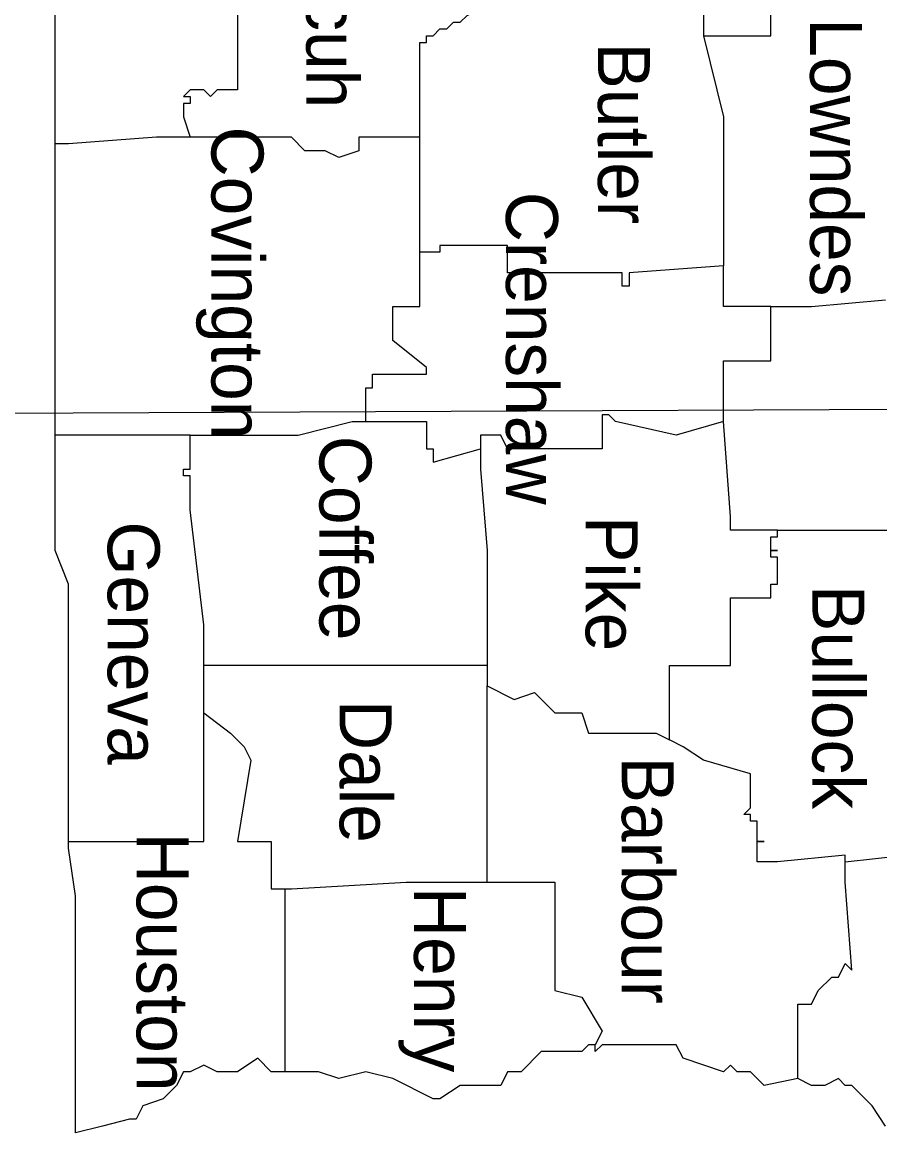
# Model space of a CAD drawing. Extents: x 0 to 0.917, y 0 to 0.708.
# Drawn here: x 0.3538 to 0.4398, y 0.4308 to 0.5421 of the extents above; entities that cross this region are included whole.
import ezdxf

# ---------------------------------------------------------------- set-up
doc = ezdxf.new("R2010")
doc.units = 0
doc.layers.add('ANNO-SHT', color=7, linetype='Continuous')
doc.layers.add('ANNO-TXT', color=7, linetype='Continuous')

msp = doc.modelspace()

# ---------------------------------------------------------------- linework, layer by layer
at = {"layer": 'ANNO-SHT'}
msp.add_line((0.44418, 0.5033), (0.34372, 0.50284), dxfattribs=at)
for points in [[(0.35711, 0.5299), (0.35711, 0.53057), (0.35711, 0.53261), (0.35711, 0.55094), (0.35711, 0.56383), (0.35711, 0.57741), (0.35711, 0.58351), (0.3544, 0.58284), (0.35373, 0.58351)], [(0.37538, 0.55094), (0.37538, 0.53533), (0.3747, 0.53533), (0.3747, 0.53533), (0.37335, 0.53533), (0.37335, 0.53533), (0.37267, 0.53465), (0.372, 0.53533), (0.372, 0.53533), (0.37064, 0.53533), (0.37064, 0.53533), (0.37064, 0.53533), (0.36997, 0.53465), (0.36997, 0.53465), (0.36997, 0.53465), (0.37064, 0.53465), (0.37064, 0.53397), (0.36997, 0.53397), (0.36997, 0.53329), (0.36997, 0.53329), (0.36997, 0.53329), (0.36997, 0.53261), (0.36997, 0.53261), (0.36997, 0.53261), (0.36997, 0.53261), (0.37064, 0.53057), (0.37064, 0.53057)], [(0.39365, 0.53057), (0.39365, 0.53261), (0.39365, 0.53397), (0.39365, 0.54008), (0.39433, 0.54008), (0.39433, 0.54075), (0.395, 0.54075), (0.39568, 0.54143), (0.39636, 0.54143), (0.39703, 0.54211), (0.39771, 0.54211), (0.39839, 0.54279), (0.39974, 0.54347), (0.40042, 0.54347), (0.4038, 0.54347), (0.40448, 0.54347), (0.40921, 0.54347)], [(0.39365, 0.53057), (0.39365, 0.53261), (0.39365, 0.53397), (0.39365, 0.54008), (0.39433, 0.54008), (0.39433, 0.54075), (0.395, 0.54075), (0.39568, 0.54143), (0.39636, 0.54143), (0.39703, 0.54211), (0.39771, 0.54211), (0.39839, 0.54279), (0.39974, 0.54347), (0.40042, 0.54347), (0.4038, 0.54347), (0.40448, 0.54347), (0.40921, 0.54347)], [(0.42207, 0.54347), (0.42207, 0.54075), (0.42613, 0.54075), (0.42816, 0.54075), (0.42884, 0.54075), (0.42884, 0.54347)], [(0.42207, 0.54347), (0.42207, 0.54075), (0.42613, 0.54075), (0.42816, 0.54075), (0.42884, 0.54075), (0.42884, 0.54347)], [(0.42207, 0.54075), (0.4241, 0.53261), (0.4241, 0.5265), (0.4241, 0.52175), (0.4241, 0.51971), (0.4241, 0.51768)], [(0.39365, 0.53057), (0.3923, 0.53057), (0.38756, 0.53057), (0.38756, 0.52922), (0.38553, 0.52854), (0.38418, 0.52922), (0.38215, 0.52922), (0.38079, 0.53057), (0.37064, 0.53057), (0.36726, 0.53057), (0.35846, 0.5299), (0.35846, 0.5299), (0.35711, 0.5299)], [(0.39365, 0.53057), (0.3923, 0.53057), (0.38756, 0.53057), (0.38756, 0.52922), (0.38553, 0.52854), (0.38418, 0.52922), (0.38215, 0.52922), (0.38079, 0.53057), (0.37064, 0.53057), (0.36726, 0.53057), (0.35846, 0.5299), (0.35846, 0.5299), (0.35711, 0.5299)], [(0.39365, 0.53057), (0.3923, 0.53057), (0.38756, 0.53057), (0.38756, 0.52922), (0.38553, 0.52854), (0.38418, 0.52922), (0.38215, 0.52922), (0.38079, 0.53057), (0.37064, 0.53057), (0.36726, 0.53057), (0.35846, 0.5299), (0.35846, 0.5299), (0.35711, 0.5299)], [(0.43154, 0.43623), (0.42816, 0.43555), (0.42681, 0.43691), (0.42545, 0.43691), (0.42478, 0.43759), (0.4241, 0.43691), (0.42004, 0.43827), (0.41936, 0.43963), (0.41327, 0.43963), (0.41192, 0.43963), (0.41124, 0.43895), (0.41124, 0.43963), (0.41057, 0.43963), (0.40989, 0.43895), (0.40854, 0.43895), (0.40583, 0.43895), (0.4038, 0.43691), (0.40245, 0.43691), (0.40177, 0.43555), (0.40042, 0.43555), (0.40042, 0.43555), (0.39771, 0.43555), (0.39568, 0.4342), (0.395, 0.4342), (0.39094, 0.43623), (0.38824, 0.43691), (0.38553, 0.43623), (0.3835, 0.43691), (0.38012, 0.43691), (0.37876, 0.43691), (0.37741, 0.43827), (0.37538, 0.43691), (0.37335, 0.43691), (0.372, 0.43759), (0.37064, 0.43691), (0.36997, 0.43691), (0.36929, 0.43555), (0.36794, 0.4342), (0.36591, 0.43352), (0.36523, 0.43216), (0.36455, 0.43216), (0.36185, 0.43148), (0.35914, 0.4308), (0.35914, 0.43352), (0.35914, 0.4437), (0.35914, 0.45456), (0.35846, 0.45931), (0.35846, 0.45999), (0.35846, 0.4627), (0.35846, 0.46881), (0.35846, 0.48578), (0.35711, 0.48917), (0.35711, 0.49732), (0.35711, 0.50071), (0.35711, 0.5075), (0.35711, 0.50886), (0.35711, 0.52718), (0.35711, 0.5299)], [(0.39365, 0.51904), (0.39365, 0.53057)], [(0.39365, 0.51904), (0.39365, 0.53057)], [(0.39365, 0.51904), (0.39365, 0.53057)], [(0.37064, 0.50071), (0.3747, 0.50071), (0.37673, 0.50071), (0.38147, 0.50071), (0.38688, 0.50207), (0.38824, 0.50207), (0.38824, 0.50546), (0.38824, 0.50546), (0.38891, 0.50546), (0.38891, 0.50682), (0.39433, 0.50682), (0.39433, 0.5075), (0.39094, 0.51021), (0.39094, 0.51157), (0.39094, 0.51361), (0.39162, 0.51361), (0.39365, 0.51361), (0.39365, 0.51904)], [(0.42884, 0.51361), (0.42884, 0.51361), (0.42884, 0.51361), (0.42816, 0.51361), (0.42816, 0.51361), (0.4241, 0.51361), (0.4241, 0.51428), (0.4241, 0.51768), (0.41463, 0.517), (0.41463, 0.517), (0.41463, 0.517), (0.41463, 0.51564), (0.41395, 0.51564), (0.41395, 0.517), (0.41395, 0.517), (0.41395, 0.517), (0.41057, 0.517), (0.41057, 0.517), (0.40989, 0.517), (0.40989, 0.517), (0.40921, 0.517), (0.40515, 0.517), (0.40245, 0.517), (0.40245, 0.51971), (0.40042, 0.51971), (0.39636, 0.51971), (0.39636, 0.51971), (0.39568, 0.51971), (0.39568, 0.51904), (0.39365, 0.51904)], [(0.42884, 0.51361), (0.42884, 0.51361), (0.42884, 0.51361), (0.42816, 0.51361), (0.42816, 0.51361), (0.4241, 0.51361), (0.4241, 0.51428), (0.4241, 0.51768), (0.41463, 0.517), (0.41463, 0.517), (0.41463, 0.517), (0.41463, 0.51564), (0.41395, 0.51564), (0.41395, 0.517), (0.41395, 0.517), (0.41395, 0.517), (0.41057, 0.517), (0.41057, 0.517), (0.40989, 0.517), (0.40989, 0.517), (0.40921, 0.517), (0.40515, 0.517), (0.40245, 0.517), (0.40245, 0.51971), (0.40042, 0.51971), (0.39636, 0.51971), (0.39636, 0.51971), (0.39568, 0.51971), (0.39568, 0.51904), (0.39365, 0.51904)], [(0.42884, 0.51361), (0.42884, 0.51361), (0.42884, 0.51361), (0.42816, 0.51361), (0.42816, 0.51361), (0.4241, 0.51361), (0.4241, 0.51428), (0.4241, 0.51768), (0.41463, 0.517), (0.41463, 0.517), (0.41463, 0.517), (0.41463, 0.51564), (0.41395, 0.51564), (0.41395, 0.517), (0.41395, 0.517), (0.41395, 0.517), (0.41057, 0.517), (0.41057, 0.517), (0.40989, 0.517), (0.40989, 0.517), (0.40921, 0.517), (0.40515, 0.517), (0.40245, 0.517), (0.40245, 0.51971), (0.40042, 0.51971), (0.39636, 0.51971), (0.39636, 0.51971), (0.39568, 0.51971), (0.39568, 0.51904), (0.39365, 0.51904)], [(0.42884, 0.51361), (0.42951, 0.51361), (0.4329, 0.51361), (0.44034, 0.51428)], [(0.4241, 0.50207), (0.4241, 0.50818), (0.4241, 0.50818), (0.42884, 0.50818), (0.42884, 0.51361), (0.42884, 0.51361)], [(0.4241, 0.50207), (0.4241, 0.50818), (0.4241, 0.50818), (0.42884, 0.50818), (0.42884, 0.51361), (0.42884, 0.51361)], [(0.4241, 0.50207), (0.4241, 0.50818), (0.4241, 0.50818), (0.42884, 0.50818), (0.42884, 0.51361), (0.42884, 0.51361)], [(0.38824, 0.50207), (0.39162, 0.50207), (0.39433, 0.50207), (0.39433, 0.50207), (0.39433, 0.49935), (0.395, 0.49935), (0.395, 0.498), (0.39974, 0.49935)], [(0.4241, 0.50207), (0.41936, 0.50071), (0.41327, 0.50207), (0.4126, 0.50275), (0.41192, 0.50275), (0.41192, 0.50003), (0.41192, 0.49935), (0.40312, 0.49935)], [(0.41869, 0.47017), (0.41869, 0.47492), (0.41869, 0.47763), (0.42478, 0.47763), (0.42478, 0.47899), (0.42478, 0.48442), (0.42545, 0.48442), (0.42545, 0.48442), (0.42613, 0.48442), (0.42613, 0.48442), (0.42884, 0.48442), (0.42884, 0.48578), (0.42951, 0.48578), (0.42951, 0.48781), (0.42951, 0.48781), (0.42951, 0.48781), (0.42951, 0.48781), (0.42951, 0.48849), (0.42951, 0.48849), (0.42951, 0.48849), (0.42884, 0.48849), (0.42884, 0.48917), (0.42951, 0.48917), (0.42951, 0.48917), (0.42884, 0.48917), (0.42884, 0.49053), (0.42951, 0.49053), (0.42951, 0.49121), (0.42478, 0.49121), (0.42478, 0.49257), (0.4241, 0.50207)], [(0.41869, 0.47017), (0.41869, 0.47492), (0.41869, 0.47763), (0.42478, 0.47763), (0.42478, 0.47899), (0.42478, 0.48442), (0.42545, 0.48442), (0.42545, 0.48442), (0.42613, 0.48442), (0.42613, 0.48442), (0.42884, 0.48442), (0.42884, 0.48578), (0.42951, 0.48578), (0.42951, 0.48781), (0.42951, 0.48781), (0.42951, 0.48781), (0.42951, 0.48781), (0.42951, 0.48849), (0.42951, 0.48849), (0.42951, 0.48849), (0.42884, 0.48849), (0.42884, 0.48917), (0.42951, 0.48917), (0.42951, 0.48917), (0.42884, 0.48917), (0.42884, 0.49053), (0.42951, 0.49053), (0.42951, 0.49121), (0.42478, 0.49121), (0.42478, 0.49257), (0.4241, 0.50207)], [(0.41869, 0.47017), (0.41869, 0.47492), (0.41869, 0.47763), (0.42478, 0.47763), (0.42478, 0.47899), (0.42478, 0.48442), (0.42545, 0.48442), (0.42545, 0.48442), (0.42613, 0.48442), (0.42613, 0.48442), (0.42884, 0.48442), (0.42884, 0.48578), (0.42951, 0.48578), (0.42951, 0.48781), (0.42951, 0.48781), (0.42951, 0.48781), (0.42951, 0.48781), (0.42951, 0.48849), (0.42951, 0.48849), (0.42951, 0.48849), (0.42884, 0.48849), (0.42884, 0.48917), (0.42951, 0.48917), (0.42951, 0.48917), (0.42884, 0.48917), (0.42884, 0.49053), (0.42951, 0.49053), (0.42951, 0.49121), (0.42478, 0.49121), (0.42478, 0.49257), (0.4241, 0.50207)], [(0.37064, 0.50071), (0.36591, 0.50071), (0.35846, 0.50071), (0.35846, 0.50071), (0.35711, 0.50071)], [(0.35846, 0.45999), (0.36252, 0.45999), (0.36997, 0.45999), (0.372, 0.45999), (0.372, 0.46677), (0.372, 0.46677), (0.372, 0.46813), (0.372, 0.47288), (0.372, 0.47628), (0.372, 0.47628), (0.372, 0.47763), (0.372, 0.48171), (0.37064, 0.49324), (0.37064, 0.49664), (0.36997, 0.49664), (0.36997, 0.49732), (0.37064, 0.49732), (0.37064, 0.49935), (0.37064, 0.50071)], [(0.40312, 0.49935), (0.40245, 0.49935), (0.40177, 0.50071), (0.39974, 0.50071), (0.39974, 0.49732), (0.40042, 0.48917), (0.40042, 0.48781), (0.40042, 0.48306), (0.40042, 0.47831), (0.40042, 0.47763), (0.40042, 0.4756), (0.40312, 0.47424), (0.40515, 0.47492), (0.40718, 0.47288), (0.40989, 0.47288), (0.41057, 0.47085), (0.41192, 0.47085), (0.41327, 0.47085), (0.41463, 0.47085), (0.41733, 0.47085), (0.41869, 0.47017)], [(0.42951, 0.49121), (0.4356, 0.49121), (0.44305, 0.49121), (0.44305, 0.49053), (0.4444, 0.49053), (0.4444, 0.49053), (0.4444, 0.48578), (0.4444, 0.4851), (0.44711, 0.4851), (0.44711, 0.48442), (0.44643, 0.48442), (0.44643, 0.48442), (0.4444, 0.48374), (0.44372, 0.48442), (0.44305, 0.48374), (0.44305, 0.48374), (0.44237, 0.48306), (0.44237, 0.48306), (0.44237, 0.47492), (0.44237, 0.45863)], [(0.40042, 0.47763), (0.39839, 0.47763), (0.395, 0.47763), (0.38688, 0.47763), (0.38079, 0.47763), (0.37876, 0.47763), (0.37538, 0.47763), (0.3747, 0.47763), (0.372, 0.47763)], [(0.372, 0.47288), (0.3747, 0.47085), (0.37606, 0.46949), (0.37673, 0.46813), (0.37606, 0.46406), (0.37538, 0.45999), (0.37876, 0.45999), (0.37876, 0.45931), (0.37876, 0.45524), (0.38079, 0.45524), (0.3923, 0.45592), (0.40042, 0.45592), (0.40042, 0.45592), (0.40042, 0.45999), (0.40042, 0.4722), (0.40042, 0.4756)], [(0.43628, 0.45863), (0.42951, 0.45795), (0.42748, 0.45795), (0.42748, 0.45999), (0.42816, 0.45999), (0.42816, 0.45999), (0.42748, 0.45999), (0.42748, 0.46202), (0.42681, 0.46202), (0.42681, 0.4627), (0.42681, 0.4627), (0.42613, 0.4627), (0.42681, 0.46338), (0.42681, 0.46677), (0.42207, 0.46813), (0.42004, 0.46949), (0.41869, 0.47017)], [(0.43628, 0.45863), (0.42951, 0.45795), (0.42748, 0.45795), (0.42748, 0.45999), (0.42816, 0.45999), (0.42816, 0.45999), (0.42748, 0.45999), (0.42748, 0.46202), (0.42681, 0.46202), (0.42681, 0.4627), (0.42681, 0.4627), (0.42613, 0.4627), (0.42681, 0.46338), (0.42681, 0.46677), (0.42207, 0.46813), (0.42004, 0.46949), (0.41869, 0.47017)], [(0.43628, 0.45863), (0.42951, 0.45795), (0.42748, 0.45795), (0.42748, 0.45999), (0.42816, 0.45999), (0.42816, 0.45999), (0.42748, 0.45999), (0.42748, 0.46202), (0.42681, 0.46202), (0.42681, 0.4627), (0.42681, 0.4627), (0.42613, 0.4627), (0.42681, 0.46338), (0.42681, 0.46677), (0.42207, 0.46813), (0.42004, 0.46949), (0.41869, 0.47017)], [(0.43628, 0.45592), (0.43628, 0.45795), (0.44237, 0.45863), (0.44237, 0.45863), (0.44372, 0.45863), (0.45455, 0.45863)], [(0.43628, 0.45795), (0.44237, 0.45863), (0.44237, 0.45863), (0.44372, 0.45863), (0.45455, 0.45863)], [(0.43628, 0.45795), (0.43628, 0.45863)], [(0.43628, 0.45592), (0.43628, 0.45795)], [(0.43628, 0.45592), (0.43628, 0.45795)], [(0.38012, 0.45524), (0.38012, 0.45184), (0.38012, 0.43759), (0.38012, 0.43759), (0.38012, 0.43691)], [(0.40042, 0.45592), (0.40177, 0.45592), (0.40718, 0.45592), (0.40718, 0.44777), (0.40718, 0.44506), (0.40989, 0.44438), (0.41192, 0.44098), (0.41124, 0.43963)], [(0.43154, 0.43623), (0.43154, 0.43759), (0.43154, 0.43827), (0.43154, 0.43827), (0.43154, 0.43895), (0.43154, 0.43895), (0.43154, 0.44098), (0.43154, 0.4437), (0.4329, 0.4437), (0.43357, 0.44506), (0.43493, 0.44641), (0.43493, 0.44641), (0.4356, 0.44641), (0.4356, 0.44641), (0.43628, 0.44777), (0.43696, 0.44709), (0.43628, 0.45592)], [(0.43154, 0.43623), (0.43154, 0.43759), (0.43154, 0.43827), (0.43154, 0.43827), (0.43154, 0.43895), (0.43154, 0.43895), (0.43154, 0.44098), (0.43154, 0.4437), (0.4329, 0.4437), (0.43357, 0.44506), (0.43493, 0.44641), (0.43493, 0.44641), (0.4356, 0.44641), (0.4356, 0.44641), (0.43628, 0.44777), (0.43696, 0.44709), (0.43628, 0.45592)], [(0.44034, 0.43148), (0.43899, 0.43352), (0.43696, 0.43555), (0.43628, 0.43555), (0.4356, 0.43623), (0.43425, 0.43555), (0.4329, 0.43555), (0.43154, 0.43623)]]:
    msp.add_lwpolyline(points, dxfattribs=at)

# ---------------------------------------------------------------- texts
at = {"layer": 'ANNO-TXT'}
for s, p in [('Conecuh', (0.38228, 0.56135)), ('Lowndes', (0.43277, 0.5425)), ('Butler', (0.41151, 0.54007)), ('Covington', (0.37278, 0.53165)), ('Crenshaw', (0.40229, 0.52511)), ('Coffee', (0.3836, 0.50066)), ('Pike', (0.41028, 0.49261)), ('Geneva', (0.36238, 0.49207)), ('Bullock', (0.433, 0.4857)), ('Dale', (0.38563, 0.47418)), ('Barbour', (0.4139, 0.4685)), ('Houston', (0.36528, 0.46088)), ('Henry', (0.39308, 0.45544))]:
    msp.add_text(s, height=0.005208, rotation=270, dxfattribs=at).set_placement(p)

doc.saveas('drawing.dxf')
